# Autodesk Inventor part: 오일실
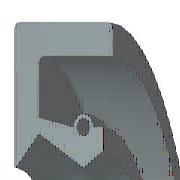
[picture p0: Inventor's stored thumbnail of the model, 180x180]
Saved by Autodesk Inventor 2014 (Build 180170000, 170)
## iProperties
IsCustomPart: 0
Manager: KYOUNG IL JANG
Company: 한국ATC센터
Created: 2009-02
Part Number: 오일실
Material: Rubber
Description: 오일-실
Document SubType Name: Modeling
Standard: KS B 2804
Standards Organization: KS
Language: ko-KR
Size Designation: D - 20 35 8
Categories: <MemberInstance><Categories><Category DisplayName="샤프트 부품" InternalName="7f7aeb1f-a693-4053-b835-cee3144e0d98" Mnemonic="SHFT"><Category DisplayName="실링" Intern
Density: 0.93 g/cm^3
Checked By: KYOUNG IL JANG
Vendor: CBT Solutions
Designer: KYOUNG IL JANG
Appearance: Rubber - Black - Version 1.1
Author: KYOUNG IL JANG
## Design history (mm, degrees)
revolve "본체" stored, may be unused: angle "d17" = 90 deg
revolve "스프링1" stored, may be unused: angle "d18" = 90 deg
body "Solid1"
sketch "스케치1"
  geometry: L1 (0, 17.5)-(8, 17.5); L2 (8, 15.75)-(1.75, 15.75); L3 (1.75, 11.75)-(4.9, 10); L4 (4.9, 10)-(0, 10); L5 (0, 0)-(9.586, 0) reference; L6 (4.9, 10)-(6.3, 10.875); L7 (0, 18)-(0, -3) reference; L8 (-1.941, 0)-(11.507, 0) reference; L9 (4.2, 12.1)-(1.75, 12.71); L10 (1.75, 12.71)-(1.75, 15.75); L11 (0, 17.5)-(0, 10.088); L12 (4.9, 10)-(0, 10); L13 (1.75, 11.75)-(0.152, 10.028); L14 (8, 17.5)-(8, 15.75); L15 (5.6, 12.1)-(6.3, 12.1); L16 (6.3, 12.1)-(6.3, 10.875); C1 r 0.455 at (4.9, 12.1); A1 r 0.7 centre (4.9, 12.1) between (5.6, 12.1) and (4.2, 12.1); A2 r 0.088 centre (0.088, 10.088) between (0, 10.088) and (0.152, 10.028); 1 further point
  constraints: 28 end point, 5 horizontal alignment, 5 point on line, 4 point on circle, 4 vertical alignment, 3 centre point, 3 tangent, 2 collinear, 2 horizontal, 2 perpendicular, 1 coincident, 1 parallel
  dimensions: "d0" = 35 diameter of L1 L5 (= SD2); "d1" = 1.75 distance of L1.end L2.start (= SD); "d2" = 0.91 diameter of C1 (= SPDI); "d3" = 1.4 diameter of A1 (= SPDA); "d4" = 20 diameter of L3.end L5 (= NND); "d5" = 23.5 diameter of L3.start L5 (= TKDM); "d7" = 25.42 diameter of L9.end L5 (= TKDM + 0.24 x SWDT); "d8" = 1.75 distance between parallel lines of L11 L10 (= SD); "d9" = 4.9 distance from line of L11 C1.centre (= SPDST); "d10" = 24.2 diameter of C1.centre L5 (= HLDM); "d11" = 0.0875 radius of A2 (= 0.25 x LAB); "d12" = 6.3 distance between parallel lines of L11 L16 (= SDI); "d13" = 21.75 diameter of L6.end L5 (= ABDM); "d14" = 8 distance from line of L11 L1.end (= SWDT)
fillet "모깎기1" dims "d6" = 0.3 (= RR)
other parameters: "SD2" = 35 [user parameter; used in 1 equation term], "SWDT" = 8 [user parameter; used in 2 equation terms], "RR" = 0.3 [user parameter; used in 1 equation term], "SD" = 1.75 [user parameter; used in 2 equation terms], "NND" = 20 [user parameter; used in 1 equation term], "SPDA" = 1.4 [user parameter; used in 1 equation term], "SPDI" = 0.91 [user parameter; used in 1 equation term], "TKDM" = 23.5 [user parameter; used in 2 equation terms], "HLDM" = 24.2 [user parameter; used in 1 equation term], "ABDM" = 21.75 [user parameter; used in 1 equation term], "SDI" = 6.3 [user parameter; used in 1 equation term], "SPDST" = 4.9 [user parameter; used in 1 equation term], "LAB" = 0.35 [user parameter; used in 1 equation term], "d15" = 0, "d16" = 0, "d19" = 0
